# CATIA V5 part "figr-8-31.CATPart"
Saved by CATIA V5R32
Part number: Part1
Bounding box of the stored display mesh (mm): x -50 to 50, y -75 to 125, z 0 to 40
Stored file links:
  D:\PROJECTS\Project 2022\CATIA V5 6R 2022\Resources\Part Files\c08_catia_v5_6r2022_prt\figr-8-31.CATPart
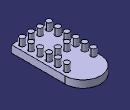
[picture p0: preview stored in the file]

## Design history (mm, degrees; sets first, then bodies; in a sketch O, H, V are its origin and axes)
Body1 (main body)
  Sketch1 on xy-plane, origin (0, 0, 0), H (1, 0, 0), V (0, 1, 0)
    line L1 (50, 75) -> (50, -75)
    line L2 (50, -75) -> (-50, -75)
    line L3 (-50, -75) -> (-50, 75)
    arc A1 centre (0, 75) radius 50 from (-50, 75) to (50, 75) cw
    point P5 (0, 75)
    axis line L4 (50, -75) -> (-50, 75)
    length L2 = 100
    distance P5 L2 = 150
    horizontal: L2 H
    vertical: L1 V, L3 V
    tangency: A1 L3, A1 L1
    midpoint: O L4
  Pad1: profile Sketch1, direction (0, 0, 1), length 20
  Sketch2 on face of Pad1, origin (0, 0, 20), H (1, 0, 0), V (0, 1, 0)
    circle A1 centre (35, -60) radius 7.5
    point P1 (35, -60)
    reference projected line E1 (-50, -75) -> (50, -75) from edge [face of Pad1 | face of Pad1]
    reference projected line E2 (50, -75) -> (50, 75) from edge [face of Pad1 | face of Pad1]
    distance P1 E1 = 15
    distance P1 E2 = 15
    radius A1 = 7.5
  Pad2: profile Sketch2, direction (0, 0, 1), length 20
  RectPattern1: of Pad2, direction 1 instances 4, spacing 25, along edge [face of Pad1 | face of Pad1] reversed, direction 2 instances 6, spacing 25, along edge [face of Pad1 | face of Pad1]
